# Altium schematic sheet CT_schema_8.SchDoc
size 281 x 153 mm
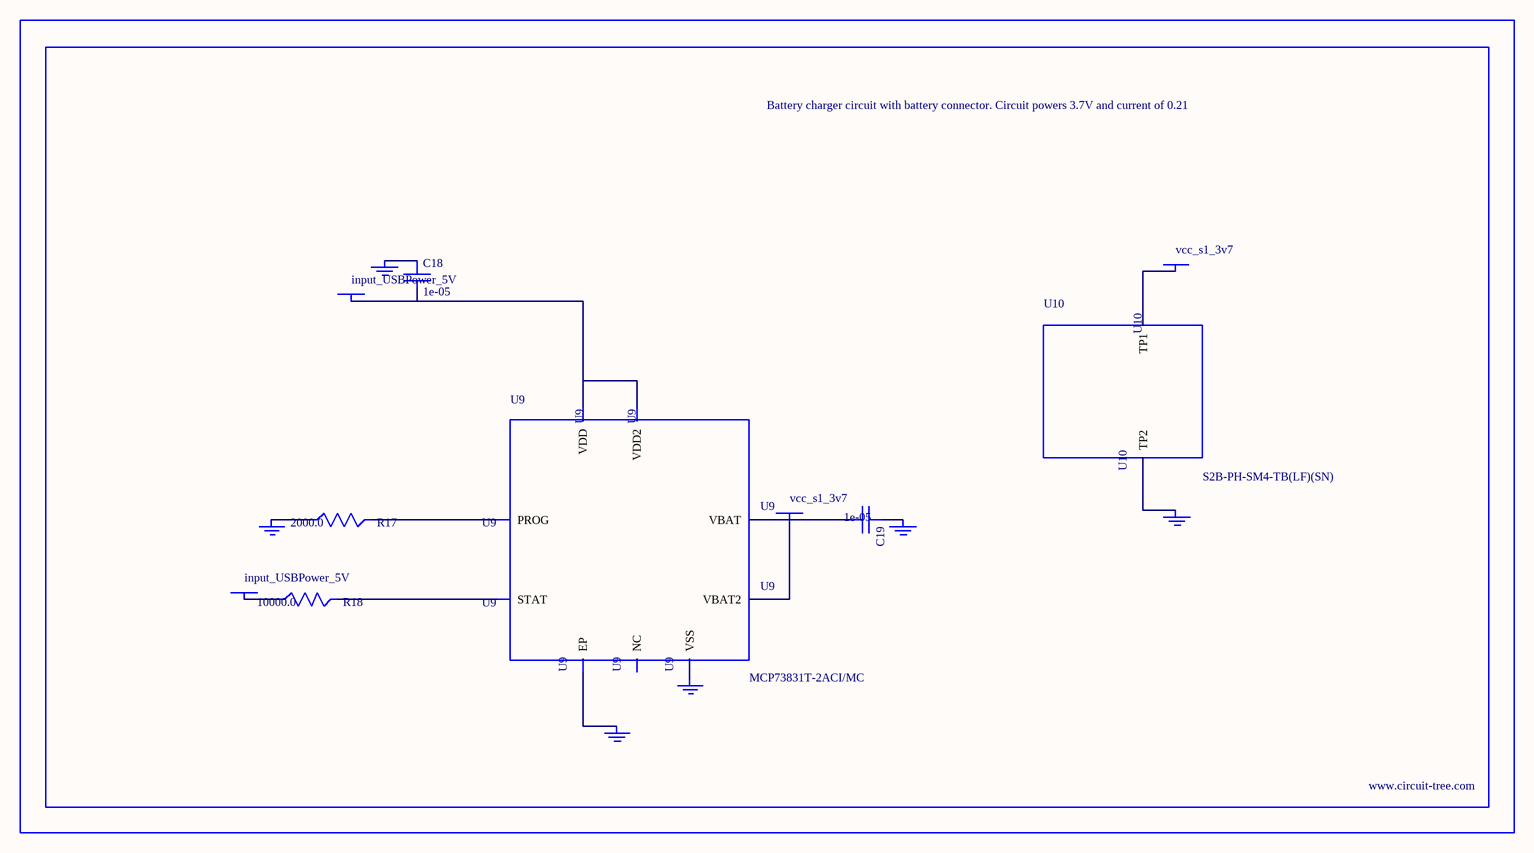
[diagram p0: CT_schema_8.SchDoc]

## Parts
BORDER7  (no value)
C18  1e-05  [C1206]
C19  1e-05  [C1206]
GND_INSTANCE_7_0  (no value)
GND_INSTANCE_7_1  (no value)
GND_INSTANCE_7_2  (no value)
GND_INSTANCE_7_3  (no value)
GND_INSTANCE_7_4  (no value)
GND_INSTANCE_7_5  (no value)
POWER_INSTANCE_7_0  input_USBPower_5V
POWER_INSTANCE_7_1  input_USBPower_5V
POWER_INSTANCE_7_2  vcc_s1_3v7
POWER_INSTANCE_7_3  vcc_s1_3v7
R17  2000.0  [R0603]
R18  10000.0  [R0603]
U9  MCP73831T-2ACI/MC  [DFN8_2X3MC]
U10  S2B-PH-SM4-TB(LF)(SN)  [JST-2-SMD]

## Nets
NetC18_1: C18.1 GND_INSTANCE_7_0.0(GND)
NetC18_2: C18.2 POWER_INSTANCE_7_0.0(PWR) U9.1(VDD) U9.2(VDD2)
NetC19_1: C19.1 GND_INSTANCE_7_1.0(GND)
NetC19_2: C19.2 POWER_INSTANCE_7_2.0(PWR) U9.3(VBAT) U9.4(VBAT2)
NetGND_INSTANCE_7_2_0: GND_INSTANCE_7_2.0(GND) R17.1
NetGND_INSTANCE_7_3_0: GND_INSTANCE_7_3.0(GND) U9.9(EP)
NetGND_INSTANCE_7_4_0: GND_INSTANCE_7_4.0(GND) U9.6(VSS)
NetGND_INSTANCE_7_5_0: GND_INSTANCE_7_5.0(GND) U10.2(TP2)
NetPOWER_INSTANCE_7_1_0: POWER_INSTANCE_7_1.0(PWR) R18.1
NetPOWER_INSTANCE_7_3_0: POWER_INSTANCE_7_3.0(PWR) U10.1(TP1)
NetR17_2: R17.2 U9.8(PROG)
NetR18_2: R18.2 U9.5(STAT)

Not connected (* = marked no-connect by the designer): U9 7(NC)

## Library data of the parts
BORDER7 = BORDER_PAGE7
C18 C19 = C1206C106K3RACTU
GND_INSTANCE_7_0-GND_INSTANCE_7_5 = GND
POWER_INSTANCE_7_0-POWER_INSTANCE_7_3 = PWR
R17 = RC0603JR-072KL
R18 = RC0603JR-0710KL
